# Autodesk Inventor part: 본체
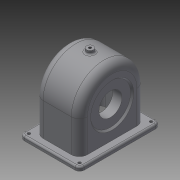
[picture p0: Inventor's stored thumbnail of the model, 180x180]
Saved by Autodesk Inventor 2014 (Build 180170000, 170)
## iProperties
Created: 2016-01
Part Number: 본체
Material: 일반
Document SubType Name: Modeling
Designer: basic
Density: 1 g/cm^3
Appearance: 기본값
Author: basic
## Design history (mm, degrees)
sketch "스케치1"
  geometry: L1 (-52, 70)-(52, 70); L2 (52, 70)-(52, -70); L3 (52, -70)-(-52, -70); L4 (-52, -70)-(-52, 70); 3 further points
  constraints: 8 end point, 2 midpoint, 2 parallel, 1 horizontal, 1 horizontal alignment, 1 perpendicular, 1 vertical alignment
  dimensions: "d0" = 104 distance of L1.start L1.end; "d1" = 140 distance of L1.end L2.end
extrude "돌출1" new body sketch "스케치1" distance "d2" = 7; taper "d3" = 0 deg
sketch "스케치2"
  geometry: L1 (-57, 7)-(-57, 64); L2 (57, 64)-(57, 7); L3 (70, 0)-(-70, 0) reference; L4 (70, 7)-(-70, 7) reference; L5 (-50.604, 7)-(57, 7); A1 r 57 centre (0, 64) between (57, 64) and (-57, 64); 2 further points
  constraints: 6 end point, 3 point on line, 2 point on circle, 2 tangent, 1 centre point, 1 collinear, 1 midpoint, 1 parallel, 1 vertical, 1 vertical alignment
  dimensions: "d4" = 64 distance from line of L3 A1.centre; "d5" = 57 radius of A1
extrude "돌출2" join sketch "스케치2" stored distance "d6" = 77; taper "d7" = 0 deg
sketch "스케치3"
  geometry: L1 (-38.5, 103.943)-(-19.5, 88); L2 (-19.5, 88)-(-19.5, 60); L3 (-19.5, 60)-(-38.5, 60); L4 (-38.5, 60)-(-38.5, 103.943); L5 (38.5, 64)-(-38.5, 64) reference; L6 (-38.5, 64)-(-38.5, 64) reference; L7 (38.5, 64)-(-38.5, 64) reference; L8 (38.5, 64)-(38.5, 64) reference; L9 (-38.5, 121)-(-38.5, 64) reference; L10 (-38.5, 64)-(-38.5, 7) reference; L11 (38.5, 64)-(38.5, 121) reference; L12 (38.5, 7)-(38.5, 64) reference; L13 (-52, 0)-(52, 0) reference; L14 (38.5, 91)-(48.5, 91); L15 (48.5, 91)-(48.5, 60); L16 (48.5, 60)-(38.5, 60); L17 (38.5, 60)-(38.5, 91); 2 further points
  constraints: 16 end point, 3 parallel, 2 collinear, 2 perpendicular, 1 horizontal, 1 midpoint, 1 point on line, 1 vertical
  dimensions: "d8" = 60 distance between parallel lines of L13 L3; "d9" = 19 distance between parallel lines of L2 L4; "d10" = 50 deg angle of L2 L1; "d11" = 56 diameter of L1.end L3; "d12" = 10 distance between parallel lines of L17 L15; "d13" = 62 diameter of L14 L16
  node "투영된 루프1"
sketch "스케치4"
  geometry: L1 (-57, 7)-(-57, 64) reference; L2 (57, 64)-(57, 7) reference; L3 (-51, 0)-(-51, 64); L4 (51, 64)-(51, 0); L5 (-70, 0)-(70, 0) reference; A1 r 57 centre (0, 64) between (57, 64) and (-57, 64) reference; A2 r 51 centre (0, 64) between (51, 64) and (-51, 64); 1 further point
  constraints: 4 end point, 2 point on circle, 2 point on line, 1 centre point, 2 other
  dimensions: "d14" = 6 distance between parallel lines of L2 L4
extrude "돌출3" cut sketch "스케치4" stored distance "d15" = 67; taper "d16" = 0 deg
revolve "회전1" stored, may be unused: angle "d17" = 90 deg
fillet "모깎기1" dims "d18" = 8
hole "구멍1" diameter "d21" = 5; stored, may be unused: countersink angle "d25" = 90 deg, drill point angle "d27" = 118 deg; dims "d19" = 10, "d20" = 10, "d22" = 6, "d23" = 4, "d24" = 2, "d26" = 8
hole "구멍2" diameter "d30" = 5; stored, may be unused: countersink angle "d34" = 90 deg, drill point angle "d36" = 118 deg; dims "d28" = 10, "d29" = 10, "d31" = 6, "d32" = 4, "d33" = 2, "d35" = 8
hole "구멍3" diameter "d39" = 5; stored, may be unused: countersink angle "d43" = 90 deg, drill point angle "d45" = 118 deg; dims "d37" = 10, "d38" = 10, "d40" = 6, "d41" = 4, "d42" = 2, "d44" = 8
hole "구멍4" diameter "d48" = 5; stored, may be unused: countersink angle "d52" = 90 deg, drill point angle "d54" = 118 deg; dims "d46" = 10, "d47" = 10, "d49" = 6, "d50" = 4, "d51" = 2, "d53" = 8
fillet "모깎기2" dims "d55" = 3
fillet "모깎기3" dims "d56" = 14, "d57" = 9
node "작업 평면1"
sketch "스케치5"
  geometry: C1 r 6 at (0, 0); 1 further point
  constraints: 1 centre point, 1 coincident
  dimensions: "d59" = 12 diameter of C1
extrude "돌출4" join sketch "스케치5" stored distance "d60" = 67; taper "d61" = 0 deg
fillet "모깎기4" dims "d62" = 3
hole "구멍5" diameter "d65" = 4.459; stored, may be unused: countersink angle "d69" = 90 deg, drill point angle "d71" = 118 deg; dims "d63" = 10, "d64" = 10, "d66" = 6, "d67" = 4, "d68" = 2, "d70" = 30
sketch "스케치6"
  geometry: L1 (-38.5, 64)-(-38.5, 107) reference; L2 (-19.5, 32)-(-19.5, 88) reference; L3 (-19.5, 60)-(-38.5, 60); L4 (-38.5, 60)-(-38.5, 97.416); L5 (-38.5, 97.416)-(-35.5, 94.899); L6 (-19.5, 80)-(-19.5, 60); L7 (-33.5, 99.747)-(-19.5, 88) reference; L8 (-33.5, 64)-(-24.5, 64) reference; L9 (-24.5, 64)-(-24.5, 64) reference; L10 (-33.5, 64)-(-24.5, 64) reference; L11 (-33.5, 64)-(-33.5, 64) reference; L12 (-35.5, 80)-(-35.5, 94.899); L13 (-19.5, 80)-(-35.5, 80); 1 further point
  constraints: 12 end point, 2 collinear, 2 parallel, 2 perpendicular, 1 midpoint, 1 point on line, 1 vertical
  dimensions: "d74" = 5 distance between parallel lines of L5 L7; "d75" = 3 distance between parallel lines of L12 L1; "d76" = 40 diameter of L13 L3
revolve "회전2" sketch "스케치6" stored, may be unused: angle "d77" = 90 deg
node "솔리드1"
node "투영된 루프2"
other parameters: "d58" = 127
